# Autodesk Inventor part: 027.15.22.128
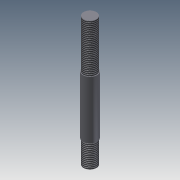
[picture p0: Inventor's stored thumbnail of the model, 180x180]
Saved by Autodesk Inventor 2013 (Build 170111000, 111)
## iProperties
Shininess: 64.0
Length Units: 11269
Angle Units: 11279
Time Units: 11290
Mass Units: 11283
Length Display Precision: 3
Angle Display Precision: 2
Created: 2002-02
Part Number: 027.15.22.128
Material: Steel, Mild
Document SubType Name: Modeling
Designer: SOleg
Density: 7.86 g/cm^3
Density: 0.0
Volumn: 0.0
Area: 0.0
PropertySet Name: Model Information
Control State: 0
Master: False
Checked Out: True
Author: SOleg
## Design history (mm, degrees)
sketch "Sketch1"
  geometry: C1 r 10 at (0, 0)
  constraints: 1 centre point
  dimensions: "d0" = 20 diameter of C1
extrude "Extrusion1" new body sketch "Sketch1" distance "d1" = 75; taper "d2" = 0 deg
sketch "Sketch2"
  geometry: C1 r 10 at (0, 0) reference; C2 r 11 at (0, 0)
  constraints: 1 centre point, 1 coincident
  dimensions: "d5" = 22 diameter of C2
extrude "Extrusion2" join sketch "Sketch2" distance "d3" = 90; taper "d4" = 0 deg
sketch "Sketch3"
  geometry: C1 r 11 at (0, 0) reference; C2 r 10 at (0, 0)
  constraints: 1 centre point, 1 coincident
  dimensions: "d6" = 20 diameter of C2
extrude "Extrusion3" join sketch "Sketch3" distance "d7" = 36; taper "d8" = 0 deg
thread "Thread1" dims "d9" = 10, "d10" = 0
thread "Thread2" dims "d11" = 10, "d12" = 0
body "Solid1"
